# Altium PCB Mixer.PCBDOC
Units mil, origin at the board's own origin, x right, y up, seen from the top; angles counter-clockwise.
Board outline 8000 x 4000 mil, 2 copper layers (Top Layer, Bottom Layer); 97 components, 56 nets, 281 pads, 0 vias.
Unrouted connection lines stored in the file: 188.
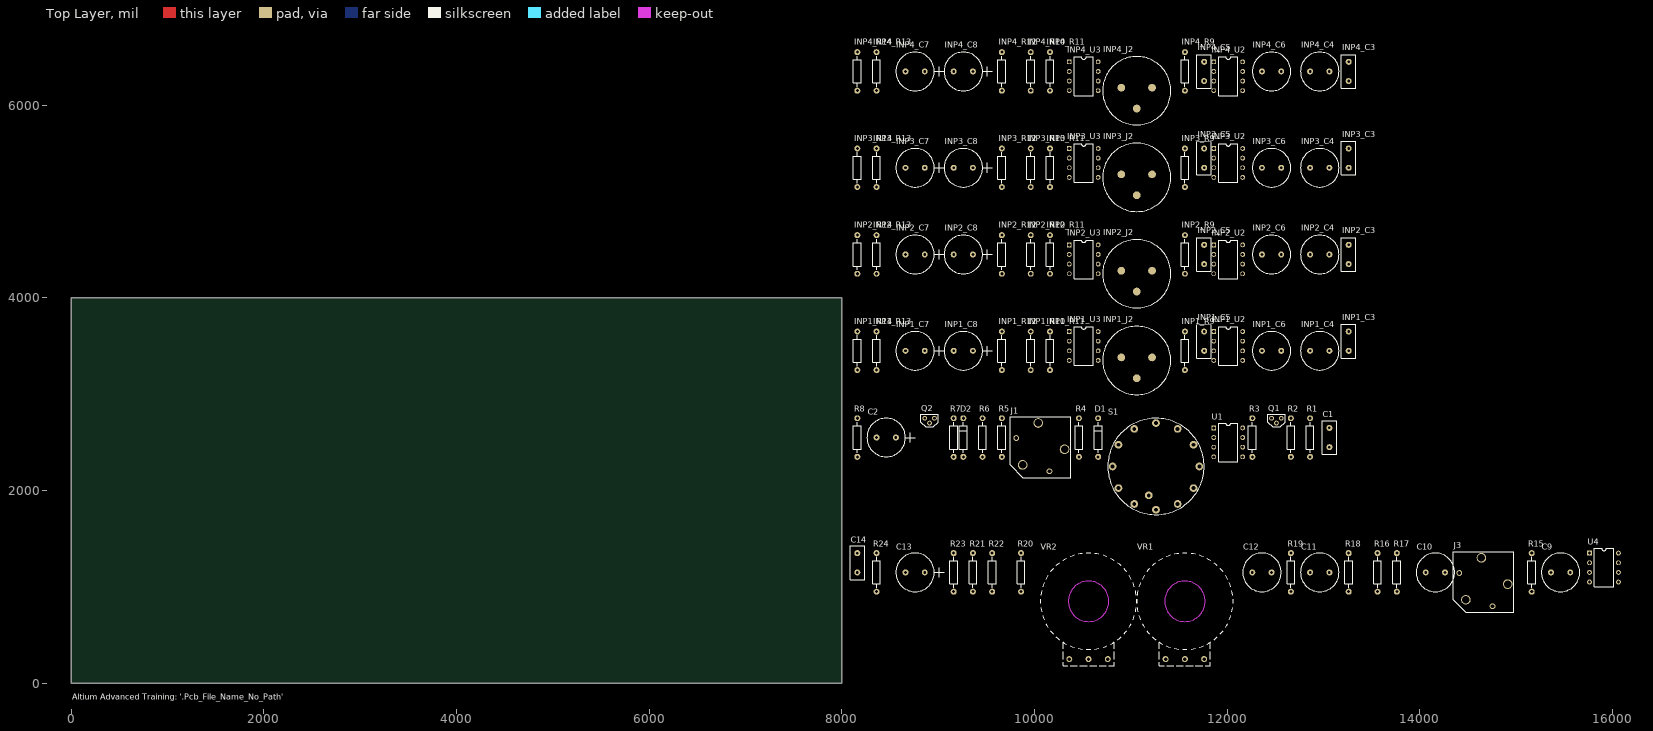
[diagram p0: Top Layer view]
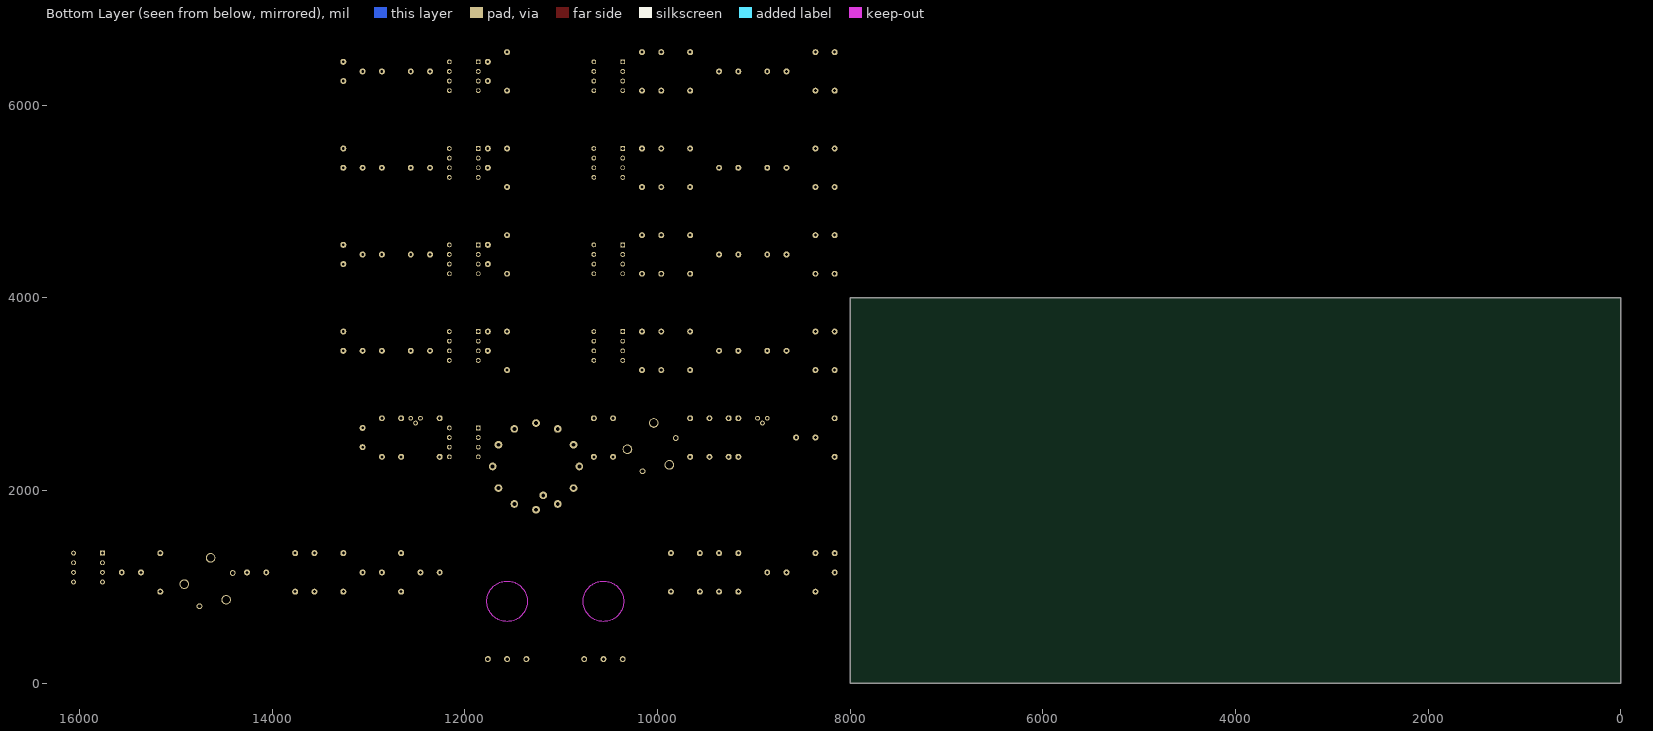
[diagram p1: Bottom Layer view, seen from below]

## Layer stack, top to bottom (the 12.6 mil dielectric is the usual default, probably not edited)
Top Solder: solder mask 0.4, Solder Resist, Dk 3.5
Top Layer: signal copper 1.4
Dielectric 1: dielectric 12.6, FR-4, Dk 4.8
Bottom Layer: signal copper 1.4
Bottom Solder: solder mask 0.4, Solder Resist, Dk 3.5

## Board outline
0,0 8000,0 8000,3000 8000,4000 0,4000 0,0

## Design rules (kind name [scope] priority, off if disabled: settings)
Clearance [All] p1: gap=20 ignorepadtopadclearanceinfootprint=FALSE except(0: Arc-Hole Track-Hole SMDPad-Hole THPad-Hole Via-Hole Fill-Hole Poly-Hole Region-Hole Text-Hole)
PolygonConnect [All] p1: connectstyle=Relief reliefconductorwidth=10 reliefentries=4 polygonreliefangle="90 Angle" airgapwidth=10
RoomDefinition INP4 [InComponentClass('INP4')] p1: confinementstyle=ConfineIn formatcopy=TRUE lockcomponents=FALSE outline 8060,5750 13360,5750 13360,6750 8060,6750
RoomDefinition INP3 [InComponentClass('INP3')] p2: confinementstyle=ConfineIn formatcopy=TRUE lockcomponents=FALSE outline 8060,4850 13360,4850 13360,5750 8060,5750
RoomDefinition INP2 [InComponentClass('INP2')] p3: confinementstyle=ConfineIn formatcopy=TRUE lockcomponents=FALSE outline 8060,3850 13360,3850 13360,4850 8060,4850
RoomDefinition INP1 [InComponentClass('INP1')] p4: confinementstyle=ConfineIn formatcopy=TRUE lockcomponents=FALSE outline 8060,2950 13360,2950 13360,3850 8060,3850
RoomDefinition HP [InComponentClass('HP')] p5: confinementstyle=ConfineIn formatcopy=TRUE lockcomponents=FALSE outline 8060,1650 13160,1650 13160,2950 8060,2950
RoomDefinition AUX [InComponentClass('AUX')] p6: confinementstyle=ConfineIn formatcopy=TRUE lockcomponents=FALSE outline 8060,150 16160,150 16160,1550 8060,1550
RoutingVias [All] p1: holewidth=28 width=50 viastyle="Through Hole" minholewidth=28 minwidth=50 maxholewidth=28 maxwidth=50
SilkToBoardRegionClearance [All] p1 off:
SilkToSilkClearance [All] p1 off: silktosilkclearance=50
SilkToSolderMaskClearance [IsPad] p1: minsilkscreentomaskgap=100 clearancetoexposedcopper=TRUE
SolderMaskExpansion [All] p1: expansion=4 istentingtop=FALSE
Width [All] p1: maxlimit=30 minlimit=10 preferedwidth=20
27 further rules are at their usual default settings.

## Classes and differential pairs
channel class "Input channel": INP1 INP2 INP3 INP4
net class MB[1..2]: MB1 MB2
net class Headphone[1..4]: Headphone1 Headphone2 Headphone3 Headphone4
component class INP4: INP4_C3 INP4_C4 INP4_C5 INP4_C6 INP4_C7 INP4_C8 INP4_J2 INP4_R9 INP4_R10 INP4_R11 INP4_R12 INP4_R13 INP4_R14 INP4_U2 INP4_U3
component class INP3: INP3_C3 INP3_C4 INP3_C5 INP3_C6 INP3_C7 INP3_C8 INP3_J2 INP3_R9 INP3_R10 INP3_R11 INP3_R12 INP3_R13 INP3_R14 INP3_U2 INP3_U3
component class INP2: INP2_C3 INP2_C4 INP2_C5 INP2_C6 INP2_C7 INP2_C8 INP2_J2 INP2_R9 INP2_R10 INP2_R11 INP2_R12 INP2_R13 INP2_R14 INP2_U2 INP2_U3
component class INP1: INP1_C3 INP1_C4 INP1_C5 INP1_C6 INP1_C7 INP1_C8 INP1_J2 INP1_R9 INP1_R10 INP1_R11 INP1_R12 INP1_R13 INP1_R14 INP1_U2 INP1_U3
component class HP: C1 C2 D1 D2 J1 Q1 Q2 R1 R2 R3 R4 R5 R6 R7 R8 S1 U1
component class AUX: C9 C10 C11 C12 C13 C14 J3 R15 R16 R17 R18 R19 R20 R21 R22 R23 R24 U4 VR1 VR2

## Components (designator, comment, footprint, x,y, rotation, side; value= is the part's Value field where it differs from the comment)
C1 "22pF" RAD0.2 13060,2450 r90 top
C2 "10uF" RB.2/.4 8560,2550 r0 top
C9 "1uF" RB.2/.4-NP 15560,1150 r0 top
C10 "2.2uF" RB.2/.4-NP 14260,1150 r0 top
C11 "1uF" RB.2/.4-NP 13060,1150 r0 top
C12 "2.2uF" RB.2/.4-NP 12460,1150 r0 top
C13 "10uF" RB.2/.4 8860,1150 r0 top
C14 "270pF" RAD0.2 8160,1150 r90 top
D1 "1N914" DIODE0.4 10660,2350 r90 top
D2 "1N914" DIODE0.4 9260,2350 r90 top
INP1_C3 "10pF" RAD0.2 13260,3450 r90 top (schematic designator C3)
INP1_C4 "6.8uF" RB.2/.4-NP 13060,3450 r0 top (schematic designator C4)
INP1_C5 "270pF" RAD0.2 11760,3450 r90 top (schematic designator C5)
INP1_C6 "2.2uF" RB.2/.4-NP 12560,3450 r0 top (schematic designator C6)
INP1_C7 "10uF" RB.2/.4 8860,3450 r0 top (schematic designator C7)
INP1_C8 "10uF" RB.2/.4 9360,3450 r0 top (schematic designator C8)
INP1_J2 "XLR" XLR-FEMALE 11060,3350 r0 top (schematic designator J2)
INP1_R9 "15k" AXIAL0.4 11560,3250 r90 top (schematic designator R9)
INP1_R10 "10k" AXIAL0.4 9960,3250 r90 top (schematic designator R10)
INP1_R11 "10k" AXIAL0.4 10160,3250 r90 top (schematic designator R11)
INP1_R12 "15k" AXIAL0.4 9660,3250 r90 top (schematic designator R12)
INP1_R13 "10k" AXIAL0.4 8360,3250 r90 top (schematic designator R13)
INP1_R14 "10k" AXIAL0.4 8160,3250 r90 top (schematic designator R14)
INP1_U2 "OP27C" DIP8 11860,3650 r0 top (schematic designator U2)
INP1_U3 "SSM2017P (8)" DIP8 10360,3650 r0 top (schematic designator U3)
INP2_C3 "10pF" RAD0.2 13260,4350 r90 top (schematic designator C3)
INP2_C4 "6.8uF" RB.2/.4-NP 13060,4450 r0 top (schematic designator C4)
INP2_C5 "270pF" RAD0.2 11760,4350 r90 top (schematic designator C5)
INP2_C6 "2.2uF" RB.2/.4-NP 12560,4450 r0 top (schematic designator C6)
INP2_C7 "10uF" RB.2/.4 8860,4450 r0 top (schematic designator C7)
INP2_C8 "10uF" RB.2/.4 9360,4450 r0 top (schematic designator C8)
INP2_J2 "XLR" XLR-FEMALE 11060,4250 r0 top (schematic designator J2)
INP2_R9 "15k" AXIAL0.4 11560,4250 r90 top (schematic designator R9)
INP2_R10 "10k" AXIAL0.4 9960,4250 r90 top (schematic designator R10)
INP2_R11 "10k" AXIAL0.4 10160,4250 r90 top (schematic designator R11)
INP2_R12 "15k" AXIAL0.4 9660,4250 r90 top (schematic designator R12)
INP2_R13 "10k" AXIAL0.4 8360,4250 r90 top (schematic designator R13)
INP2_R14 "10k" AXIAL0.4 8160,4250 r90 top (schematic designator R14)
INP2_U2 "OP27C" DIP8 11860,4550 r0 top (schematic designator U2)
INP2_U3 "SSM2017P (8)" DIP8 10360,4550 r0 top (schematic designator U3)
INP3_C3 "10pF" RAD0.2 13260,5350 r90 top (schematic designator C3)
INP3_C4 "6.8uF" RB.2/.4-NP 13060,5350 r0 top (schematic designator C4)
INP3_C5 "270pF" RAD0.2 11760,5350 r90 top (schematic designator C5)
INP3_C6 "2.2uF" RB.2/.4-NP 12560,5350 r0 top (schematic designator C6)
INP3_C7 "10uF" RB.2/.4 8860,5350 r0 top (schematic designator C7)
INP3_C8 "10uF" RB.2/.4 9360,5350 r0 top (schematic designator C8)
INP3_J2 "XLR" XLR-FEMALE 11060,5250 r0 top (schematic designator J2)
INP3_R9 "15k" AXIAL0.4 11560,5150 r90 top (schematic designator R9)
INP3_R10 "10k" AXIAL0.4 9960,5150 r90 top (schematic designator R10)
INP3_R11 "10k" AXIAL0.4 10160,5150 r90 top (schematic designator R11)
INP3_R12 "15k" AXIAL0.4 9660,5150 r90 top (schematic designator R12)
INP3_R13 "10k" AXIAL0.4 8360,5150 r90 top (schematic designator R13)
INP3_R14 "10k" AXIAL0.4 8160,5150 r90 top (schematic designator R14)
INP3_U2 "OP27C" DIP8 11860,5550 r0 top (schematic designator U2)
INP3_U3 "SSM2017P (8)" DIP8 10360,5550 r0 top (schematic designator U3)
INP4_C3 "10pF" RAD0.2 13260,6250 r90 top (schematic designator C3)
INP4_C4 "6.8uF" RB.2/.4-NP 13060,6350 r0 top (schematic designator C4)
INP4_C5 "270pF" RAD0.2 11760,6250 r90 top (schematic designator C5)
INP4_C6 "2.2uF" RB.2/.4-NP 12560,6350 r0 top (schematic designator C6)
INP4_C7 "10uF" RB.2/.4 8860,6350 r0 top (schematic designator C7)
INP4_C8 "10uF" RB.2/.4 9360,6350 r0 top (schematic designator C8)
INP4_J2 "XLR" XLR-FEMALE 11060,6150 r0 top (schematic designator J2)
INP4_R9 "15k" AXIAL0.4 11560,6150 r90 top (schematic designator R9)
INP4_R10 "10k" AXIAL0.4 9960,6150 r90 top (schematic designator R10)
INP4_R11 "10k" AXIAL0.4 10160,6150 r90 top (schematic designator R11)
INP4_R12 "15k" AXIAL0.4 9660,6150 r90 top (schematic designator R12)
INP4_R13 "10k" AXIAL0.4 8360,6150 r90 top (schematic designator R13)
INP4_R14 "10k" AXIAL0.4 8160,6150 r90 top (schematic designator R14)
INP4_U2 "OP27C" DIP8 11860,6450 r0 top (schematic designator U2)
INP4_U3 "SSM2017P (8)" DIP8 10360,6450 r0 top (schematic designator U3)
J1 "Headphone" JACK-6.25MM 10060,2450 r0 top
J3 "Auxilary In" JACK-6.25MM 14660,1050 r0 top
Q1 "BC338-25" TO-92A 12460,2750 r0 top
Q2 "BC328-25" TO-92A 8860,2750 r0 top
R1 "68k" AXIAL0.4 12860,2350 r90 top
R2 "10k" AXIAL0.4 12660,2350 r90 top
R3 "33R" AXIAL0.4 12260,2350 r90 top
R4 "10k" AXIAL0.4 10460,2350 r90 top
R5 "68R" AXIAL0.4 9660,2350 r90 top
R6 "33R" AXIAL0.4 9460,2350 r90 top
R7 "22k" AXIAL0.4 9160,2350 r90 top
R8 "10k" AXIAL0.4 8160,2350 r90 top
R15 "10R" AXIAL0.4 15160,950 r90 top
R16 "15k" AXIAL0.4 13560,950 r90 top
R17 "15k" AXIAL0.4 13760,950 r90 top
R18 "22k" AXIAL0.4 13260,950 r90 top
R19 "10R" AXIAL0.4 12660,950 r90 top
R20 "22k" AXIAL0.4 9860,950 r90 top
R21 "15k" AXIAL0.4 9360,950 r90 top
R22 "15k" AXIAL0.4 9560,950 r90 top
R23 "6.8k" AXIAL0.4 9160,950 r90 top
R24 "2.2k" AXIAL0.4 8360,950 r90 top
S1 "SW-12WAY" SW-12WAY 11260,2250 r0 top
U1 "TL071" DIP8 11860,2650 r0 top
U4 "LM833M" DIP8 15760,1350 r0 top
VR1 "10k LOG" "POT - 24MM" 11560,850 r0 top
VR2 "10k LIN" "POT - 24MM" 10560,850 r0 top

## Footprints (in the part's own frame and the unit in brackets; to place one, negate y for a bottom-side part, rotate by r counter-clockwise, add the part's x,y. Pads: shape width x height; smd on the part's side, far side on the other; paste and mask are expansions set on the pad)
AXIAL0.4 [mil]
  round 62 hole 32: 1(0,0) 2(400,0)
  silkscreen extent 40,-40 360,40
DIODE0.4 [mil]
  round 62 hole 32: 1(0,0) 2(400,0)
  silkscreen extent 40,-40 360,40
DIP8 [mil]
  rect 50x50 hole 32: 1(0,0)
  round 50 hole 32: 2(0,-100) 3(0,-200) 4(0,-300) 5(300,-300) 6(300,-200) 7(300,-100) 8(300,0)
  silkscreen extent 50,-350 250,50
JACK-6.25MM [mil]
  round 60 hole 39: 0(-251,94) 0(94,-251)
  round 100 hole 78: 1(251,-22) 2(-22,251) 3(-184,-184)
  silkscreen extent -315,-315 315,315
"POT - 24MM" [mil]
  round 62 hole 35: 1(-200,-600) 2(0,-600) 3(200,-600)
  round 50 hole 236.22 unplated mask+4: MNT(0,0)
  Keep-Out Layer circle w10: c0,0 r210
  silkscreen extent -500,-670 500,500
RAD0.2 [mil]
  round 62 hole 28: 1(0,0) 2(200,0)
  silkscreen extent -75,-75 275,75
RB.2/.4 [mil]
  round 62 hole 28: 1(0,0) 2(-200,0)
  silkscreen extent -300,-200 200,200
RB.2/.4-NP [mil]
  round 62 hole 28: 1(0,0) 2(-200,0)
  silkscreen extent -300,-200 100,200
SW-12WAY [mil]
  round 80 hole 40: 1(225,389.71) 2(389.71,225) 3(450,0) 4(389.71,-225) 5(225,-389.71) 6(0,-450) 7(-225,-389.71) 8(-389.71,-225) 9(-450,0) 10(-389.71,225) 11(-225,389.71) 12(0,450) 13(-75,-300)
  silkscreen extent -500,-500 500,500
TO-92A [mil]
  round 50 hole 30: 1(0,0) 2(50,-50) 3(100,0)
  silkscreen extent -40,-90 140,40
XLR-FEMALE [mm]
  round 2.032 smd: 1(-4.05,0.8) 2(4.05,0.8) 3(0,-4.7)
  silkscreen extent -9,-9 9,9

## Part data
C1 C9 C10 C11 C12 C14 INP1_C3 INP1_C4 INP1_C5 INP1_C6 INP2_C3 INP2_C4 INP2_C5 INP2_C6 INP3_C3 INP3_C4 INP3_C5 INP3_C6 INP4_C3 INP4_C4 INP4_C5 INP4_C6: library part CAP, "Capacitor"
C2 C13 INP1_C7 INP1_C8 INP2_C7 INP2_C8 INP3_C7 INP3_C8 INP4_C7 INP4_C8: library part "CAPACITOR POL", "Bi-Polar Capacitor"
D1 D2: "Diode"
INP1_J2 INP2_J2 INP3_J2 INP4_J2: "XLR connector, PCB mounted"
INP1_R9 INP1_R10 INP1_R11 INP1_R12 INP1_R13 INP1_R14 INP2_R9 INP2_R10 INP2_R11 INP2_R12 INP2_R13 INP2_R14 INP3_R9 INP3_R10 INP3_R11 INP3_R12 INP3_R13 INP3_R14 INP4_R9 INP4_R10 INP4_R11 INP4_R12 INP4_R13 INP4_R14 R1 R2 R3 R4 R5 R6 R7 R8 R15 R16 R17 R18 R19 R20 R21 R22 R23 R24: library part RES1, "Resistor"
INP1_U2 INP2_U2 INP3_U2 INP4_U2: "Low Noise, High Speed Precision Operational Amplifier"
INP1_U3 INP2_U3 INP3_U3 INP4_U3: "Self-Contained Audio Preamplifier"
J1 J3: library part "PHONEJACK MONO"
Q1: "NPN BJT"
Q2: "PNP BJT"
U1: "Low-Noise  JFET-Input Operational Amplifiers"
U4: "Fast Settling Dual Operational Amplifier"
VR1 VR2: library part POT1, "Potentiometer"

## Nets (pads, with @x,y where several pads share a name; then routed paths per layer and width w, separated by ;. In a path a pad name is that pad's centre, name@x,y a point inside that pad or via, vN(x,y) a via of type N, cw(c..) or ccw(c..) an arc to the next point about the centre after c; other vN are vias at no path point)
+15V: C2.1 C13.1 INP1_C7.1 INP1_C8.1 INP1_U2.7 INP1_U3.7 INP2_C7.1 INP2_C8.1 INP2_U2.7 INP2_U3.7 INP3_C7.1 INP3_C8.1 INP3_U2.7 INP3_U3.7 INP4_C7.1 INP4_C8.1 INP4_U2.7 INP4_U3.7 Q1.1 R2.2 U1.7 U4.4
-15V: C2.2 C13.2 INP1_C7.2 INP1_C8.2 INP1_U2.4 INP1_U3.4 INP2_C7.2 INP2_C8.2 INP2_U2.4 INP2_U3.4 INP3_C7.2 INP3_C8.2 INP3_U2.4 INP3_U3.4 INP4_C7.2 INP4_C8.2 INP4_U2.4 INP4_U3.4 Q2.1 R8.1 U1.4 U4.8
GND: INP1_J2.1 INP1_R10.1 INP1_R11.1 INP1_R14.1 INP1_U2.3 INP1_U3.5 INP2_J2.1 INP2_R10.1 INP2_R11.1 INP2_R14.1 INP2_U2.3 INP2_U3.5 INP3_J2.1 INP3_R10.1 INP3_R11.1 INP3_R14.1 INP3_U2.3 INP3_U3.5 INP4_J2.1 INP4_R10.1 INP4_R11.1 INP4_R14.1 INP4_U2.3 INP4_U3.5 J1.3 J3.3 R7.1 R18.1 R20.1 R24.2 VR1.3 VR2.2
Headphone1: INP1_R13.2 S1.8
Headphone2: INP2_R13.2 S1.7
Headphone3: INP3_R13.2 S1.6
Headphone4: INP4_R13.2 S1.5
MB1: INP1_R9.2 INP2_R9.2 INP3_R9.2 INP4_R9.2 R17.2 S1.11
MB2: INP1_R12.2 INP2_R12.2 INP3_R12.2 INP4_R12.2 R22.2 S1.12
NetC1_1: C1.1 R1.1 R4.2 U1.2
NetC1_2: C1.2 R1.2 R3.1 R5.1 R6.2
NetC9_1: C9.1 J3.1
NetC9_2: C9.2 R15.1 R18.2
NetC10_1: C10.1 U4.1 U4.2
NetC10_2: C10.2 VR1.1
NetC11_1: C11.1 VR1.2
NetC11_2: C11.2 R19.1 R20.2
NetC12_1: C12.1 C14.2 R23.1 U4.7
NetC12_2: C12.2 R16.1 R21.1
NetC14_1: C14.1 R23.2 R24.1 U4.6
NetD1_1: D1.1 Q1.2 R2.1
NetD1_2: D1.2 D2.1 U1.6
NetD2_2: D2.2 Q2.2 R8.2
NetINP1_C3_1: INP1_C3.1 INP1_C4.2 INP1_U2.2
NetINP1_C3_2: INP1_C3.2 INP1_C6.1 INP1_U2.6
NetINP1_C4_1: INP1_C4.1 INP1_U3.6
NetINP1_C5_1: INP1_C5.1 INP1_J2.2 INP1_R10.2 INP1_U3.2
NetINP1_C5_2: INP1_C5.2 INP1_J2.3 INP1_R11.2 INP1_U3.3
NetINP1_C6_2: INP1_C6.2 INP1_R9.1 INP1_R12.1 INP1_R13.1 INP1_R14.2
NetINP2_C3_1: INP2_C3.1 INP2_C4.2 INP2_U2.2
NetINP2_C3_2: INP2_C3.2 INP2_C6.1 INP2_U2.6
NetINP2_C4_1: INP2_C4.1 INP2_U3.6
NetINP2_C5_1: INP2_C5.1 INP2_J2.2 INP2_R10.2 INP2_U3.2
NetINP2_C5_2: INP2_C5.2 INP2_J2.3 INP2_R11.2 INP2_U3.3
NetINP2_C6_2: INP2_C6.2 INP2_R9.1 INP2_R12.1 INP2_R13.1 INP2_R14.2
NetINP3_C3_1: INP3_C3.1 INP3_C4.2 INP3_U2.2
NetINP3_C3_2: INP3_C3.2 INP3_C6.1 INP3_U2.6
NetINP3_C4_1: INP3_C4.1 INP3_U3.6
NetINP3_C5_1: INP3_C5.1 INP3_J2.2 INP3_R10.2 INP3_U3.2
NetINP3_C5_2: INP3_C5.2 INP3_J2.3 INP3_R11.2 INP3_U3.3
NetINP3_C6_2: INP3_C6.2 INP3_R9.1 INP3_R12.1 INP3_R13.1 INP3_R14.2
NetINP4_C3_1: INP4_C3.1 INP4_C4.2 INP4_U2.2
NetINP4_C3_2: INP4_C3.2 INP4_C6.1 INP4_U2.6
NetINP4_C4_1: INP4_C4.1 INP4_U3.6
NetINP4_C5_1: INP4_C5.1 INP4_J2.2 INP4_R10.2 INP4_U3.2
NetINP4_C5_2: INP4_C5.2 INP4_J2.3 INP4_R11.2 INP4_U3.3
NetINP4_C6_2: INP4_C6.2 INP4_R9.1 INP4_R12.1 INP4_R13.1 INP4_R14.2
NetJ1_1: J1.1 R5.2
NetQ1_3: Q1.3 R3.2
NetQ2_3: Q2.3 R6.1
NetR4_1: R4.1 S1.13
NetR7_2: R7.2 U1.3
NetR15_2: R15.2 U4.3
NetR16_2: R16.2 R17.1 VR2.1
NetR19_2: R19.2 U4.5
NetR21_2: R21.2 R22.1 VR2.3
pads on no net: INP1_U2.1 INP1_U2.5 INP1_U2.8 INP1_U3.1 INP1_U3.8 INP2_U2.1 INP2_U2.5 INP2_U2.8 INP2_U3.1 INP2_U3.8 INP3_U2.1 INP3_U2.5 INP3_U2.8 INP3_U3.1 INP3_U3.8 INP4_U2.1 INP4_U2.5 INP4_U2.8 INP4_U3.1 INP4_U3.8 J1.0 J1.2 J3.0 J3.2 S1.1 S1.2 S1.3 S1.4 S1.9 S1.10 U1.1 U1.5 U1.8 VR1.MNT VR2.MNT

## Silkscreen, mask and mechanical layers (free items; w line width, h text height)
Top Overlay:
  text "Altium Advanced Training: '.Pcb_File_Name_No_Path'" at 10,-170.01 h60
